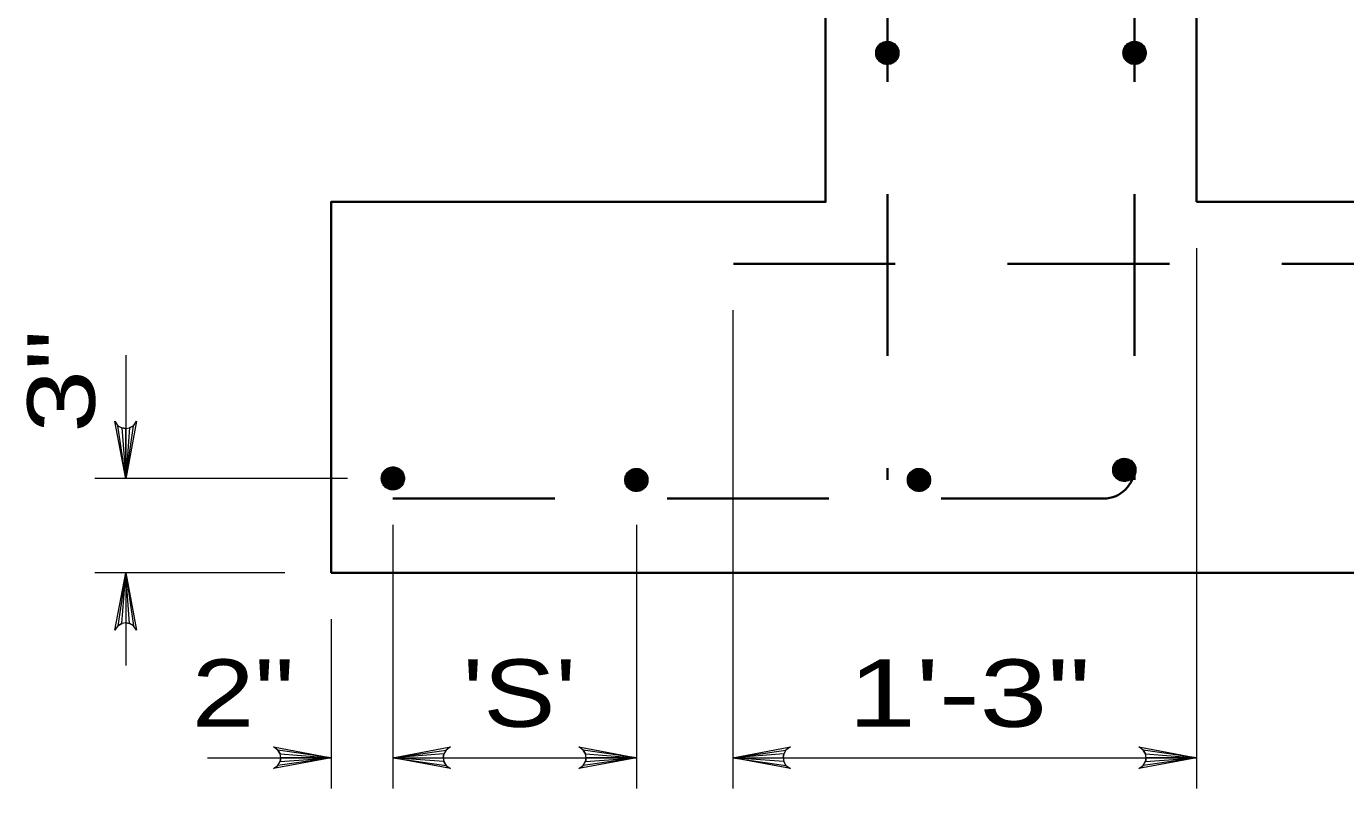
# Model space of a CAD drawing. Extents: x 394.95 to 401.96, y -76.51 to -66.78.
# Drawn here: x 399.118 to 400.292, y -68.199 to -67.52 of the extents above; entities that cross this region are included whole.
import ezdxf
from ezdxf.enums import TextEntityAlignment as Align

# ---------------------------------------------------------------- set-up
doc = ezdxf.new("R2010")
doc.units = 0
doc.header["$LTSCALE"] = 0.024
doc.linetypes.add('LONG_DASHED', pattern=[7.5, 6, -1.5])
doc.layers.add('1', color=7, linetype='LONG_DASHED', lineweight=35)
doc.layers.add('10', color=7, linetype='Continuous', lineweight=13)
doc.layers.add('12', color=7, linetype='Continuous')

msp = doc.modelspace()

# ---------------------------------------------------------------- linework, layer by layer
at = {"layer": '1', "linetype": 'Continuous'}
for p, q in [((400.15918, -67.6764), (400.15918, -67.1264)), ((399.38918, -68.0064), (400.43418, -68.0064))]:
    msp.add_line(p, q, dxfattribs=at)
at = {"layer": '1'}
for p, q in [((399.88418, -67.1814), (399.88418, -67.9239)), ((400.10418, -67.1814), (400.10418, -67.9239)), ((400.37918, -67.7314), (399.74668, -67.7314)), ((399.44418, -67.9404), (400.07668, -67.9404))]:
    msp.add_line(p, q, dxfattribs=at)
at = {"layer": '1', "linetype": 'Continuous'}
for points in [[(399.38918, -68.0064), (399.38918, -67.6764), (399.82918, -67.6764), (399.82918, -67.1264), (400.15918, -67.1264)], [(400.15918, -67.6764), (400.43418, -67.6764), (400.43418, -68.0064)]]:
    msp.add_lwpolyline(points, dxfattribs=at)
at = {"layer": '1', "lineweight": 13}
for points in [[(399.88144, -67.53425), (399.88465, -67.53369), (399.88843, -67.53481), (399.89241, -67.5383), (399.8938, -67.54164), (399.89384, -67.54565), (399.89175, -67.55014), (399.88875, -67.5528), (399.88542, -67.55364), (399.88165, -67.55352), (399.8784, -67.55195), (399.87618, -67.5499), (399.87478, -67.54681), (399.87412, -67.54335), (399.87498, -67.54015), (399.87658, -67.53742), (399.8792, -67.53525), (399.88144, -67.53432), (399.8873, -67.53437), (399.88027, -67.53477), (399.88867, -67.53481), (399.87843, -67.53536), (399.88982, -67.53557), (399.87795, -67.53601), (399.89047, -67.53609), (399.87727, -67.53654), (399.89127, -67.53678), (399.87662, -67.53714), (399.89187, -67.53729), (399.8763, -67.53774), (399.89211, -67.53782), (399.87585, -67.53818), (399.89268, -67.5383), (399.87561, -67.5385), (399.89284, -67.53878), (399.87543, -67.53902), (399.89312, -67.53914), (399.87522, -67.53943), (399.89336, -67.53958), (399.87466, -67.53999), (399.89353, -67.53999), (399.87457, -67.54059), (399.89365, -67.54031), (399.87445, -67.54127), (399.89384, -67.54095), (399.87421, -67.54204), (399.89389, -67.54148), (399.87433, -67.54172), (399.89412, -67.54196), (399.87418, -67.54252), (399.89409, -67.54247), (399.87409, -67.54296), (399.89421, -67.54287), (399.87405, -67.54341), (399.89421, -67.54324), (399.87418, -67.54404), (399.89421, -67.54372), (399.87409, -67.54452), (399.89433, -67.54424), (399.87401, -67.54376), (399.89421, -67.54469), (399.87412, -67.54493), (399.89428, -67.54512), (399.87418, -67.54536), (399.89409, -67.54561), (399.87425, -67.54577), (399.89396, -67.54601), (399.87442, -67.54629), (399.89389, -67.54636), (399.8745, -67.54674), (399.8938, -67.54685), (399.87481, -67.54725), (399.89372, -67.5473), (399.8749, -67.5477), (399.89353, -67.54761), (399.87502, -67.54818), (399.89329, -67.54802), (399.87534, -67.54861), (399.89316, -67.5485), (399.87558, -67.54902), (399.89289, -67.54894), (399.8757, -67.54939), (399.8926, -67.54946), (399.87602, -67.54978), (399.89235, -67.54982), (399.87634, -67.5501), (399.89192, -67.5503), (399.87682, -67.55062), (399.89135, -67.55078), (399.8773, -67.55118), (399.89075, -67.55131), (399.87799, -67.55186), (399.89031, -67.55171), (399.87923, -67.55251), (399.88987, -67.55227), (399.87887, -67.55227), (399.88919, -67.55264), (399.87968, -67.5528), (399.8883, -67.55307), (399.88031, -67.55311), (399.8873, -67.55344)], [(399.8873, -67.55344), (399.88373, -67.55387), (399.87843, -67.55043), (399.87519, -67.54332), (399.87995, -67.53529), (399.88691, -67.53445), (399.89228, -67.54062), (399.89228, -67.54725), (399.88891, -67.55216), (399.88333, -67.55323), (399.87703, -67.54995), (399.87931, -67.55183), (399.8753, -67.54131), (399.87906, -67.5355), (399.88461, -67.5339), (399.88871, -67.53574), (399.89216, -67.53975), (399.89369, -67.54303), (399.89187, -67.5495)], [(400.10144, -67.53425), (400.10465, -67.53369), (400.10843, -67.53481), (400.11241, -67.5383), (400.1138, -67.54164), (400.11384, -67.54565), (400.11175, -67.55014), (400.10875, -67.5528), (400.10542, -67.55364), (400.10165, -67.55352), (400.0984, -67.55195), (400.09618, -67.5499), (400.09478, -67.54681), (400.09412, -67.54335), (400.09498, -67.54015), (400.09658, -67.53742), (400.0992, -67.53525), (400.10144, -67.53432), (400.1073, -67.53437), (400.10027, -67.53477), (400.10867, -67.53481), (400.09843, -67.53536), (400.10982, -67.53557), (400.09795, -67.53601), (400.11047, -67.53609), (400.09727, -67.53654), (400.11127, -67.53678), (400.09662, -67.53714), (400.11187, -67.53729), (400.0963, -67.53774), (400.11211, -67.53782), (400.09585, -67.53818), (400.11268, -67.5383), (400.09561, -67.5385), (400.11284, -67.53878), (400.09543, -67.53902), (400.11312, -67.53914), (400.09522, -67.53943), (400.11336, -67.53958), (400.09466, -67.53999), (400.11353, -67.53999), (400.09457, -67.54059), (400.11365, -67.54031), (400.09445, -67.54127), (400.11384, -67.54095), (400.09421, -67.54204), (400.11389, -67.54148), (400.09433, -67.54172), (400.11413, -67.54196), (400.09418, -67.54252), (400.11409, -67.54247), (400.09409, -67.54296), (400.11421, -67.54287), (400.09405, -67.54341), (400.11421, -67.54324), (400.09418, -67.54404), (400.11421, -67.54372), (400.09409, -67.54452), (400.11433, -67.54424), (400.09401, -67.54376), (400.11421, -67.54469), (400.09412, -67.54493), (400.11428, -67.54512), (400.09418, -67.54536), (400.11409, -67.54561), (400.09425, -67.54577), (400.11396, -67.54601), (400.09442, -67.54629), (400.11389, -67.54636), (400.0945, -67.54674), (400.1138, -67.54685), (400.09481, -67.54725), (400.11372, -67.5473), (400.0949, -67.5477), (400.11353, -67.54761), (400.09502, -67.54818), (400.11329, -67.54802), (400.09534, -67.54861), (400.11316, -67.5485), (400.09558, -67.54902), (400.11289, -67.54894), (400.0957, -67.54939), (400.1126, -67.54946), (400.09602, -67.54978), (400.11235, -67.54982), (400.09634, -67.5501), (400.11192, -67.5503), (400.09682, -67.55062), (400.11135, -67.55078), (400.0973, -67.55118), (400.11075, -67.55131), (400.09799, -67.55186), (400.11031, -67.55171), (400.09923, -67.55251), (400.10987, -67.55227), (400.09887, -67.55227), (400.10919, -67.55264), (400.09968, -67.5528), (400.1083, -67.55307), (400.10031, -67.55311), (400.1073, -67.55344)], [(400.1073, -67.55344), (400.10373, -67.55387), (400.09843, -67.55043), (400.09519, -67.54332), (400.09995, -67.53529), (400.10691, -67.53445), (400.11228, -67.54062), (400.11228, -67.54725), (400.10891, -67.55216), (400.10333, -67.55323), (400.09703, -67.54995), (400.09931, -67.55183), (400.0953, -67.54131), (400.09906, -67.5355), (400.10461, -67.5339), (400.10871, -67.53574), (400.11216, -67.53975), (400.11369, -67.54303), (400.11187, -67.5495)], [(399.44144, -67.91296), (399.44465, -67.9124), (399.44843, -67.91352), (399.45241, -67.91701), (399.4538, -67.92033), (399.45384, -67.92435), (399.45175, -67.92884), (399.44875, -67.9315), (399.44542, -67.93234), (399.44165, -67.93222), (399.4384, -67.93066), (399.43618, -67.9286), (399.43478, -67.92551), (399.43412, -67.92206), (399.43498, -67.91885), (399.43658, -67.91612), (399.4392, -67.91395), (399.44144, -67.91303), (399.4473, -67.91307), (399.44027, -67.91347), (399.44867, -67.91352), (399.43843, -67.91408), (399.44982, -67.91427), (399.43795, -67.91472), (399.45047, -67.9148), (399.43727, -67.91524), (399.45127, -67.91548), (399.43662, -67.91584), (399.45187, -67.916), (399.4363, -67.91645), (399.45211, -67.91653), (399.43585, -67.91689), (399.45268, -67.91701), (399.43561, -67.91721), (399.45284, -67.91749), (399.43543, -67.91773), (399.45312, -67.91784), (399.43522, -67.91814), (399.45336, -67.91829), (399.43466, -67.9187), (399.45353, -67.9187), (399.43457, -67.91929), (399.45365, -67.91902), (399.43445, -67.91998), (399.45384, -67.91966), (399.43421, -67.92074), (399.45389, -67.92018), (399.43433, -67.92042), (399.45412, -67.92066), (399.43418, -67.92122), (399.45409, -67.92119), (399.43409, -67.92167), (399.45421, -67.92158), (399.43405, -67.92211), (399.45421, -67.92195), (399.43418, -67.92275), (399.45421, -67.92243), (399.43409, -67.92323), (399.45433, -67.92295), (399.43401, -67.92247), (399.45421, -67.9234), (399.43412, -67.92364), (399.45428, -67.92383), (399.43418, -67.92407), (399.45409, -67.92431), (399.43425, -67.92447), (399.45396, -67.92471), (399.43442, -67.925), (399.45389, -67.92508), (399.4345, -67.92544), (399.4538, -67.92556), (399.43481, -67.92596), (399.45372, -67.926), (399.4349, -67.9264), (399.45353, -67.92631), (399.43502, -67.92687), (399.45329, -67.92672), (399.43534, -67.92732), (399.45316, -67.9272), (399.43558, -67.92773), (399.45289, -67.92765), (399.4357, -67.92809), (399.4526, -67.92818), (399.43602, -67.92849), (399.45235, -67.92853), (399.43634, -67.92881), (399.45192, -67.92901), (399.43682, -67.92933), (399.45135, -67.92949), (399.4373, -67.9299), (399.45075, -67.93002), (399.43799, -67.93058), (399.45031, -67.93042), (399.43923, -67.93122), (399.44987, -67.93098), (399.43887, -67.93098), (399.44919, -67.93133), (399.43968, -67.9315), (399.4483, -67.93178), (399.44031, -67.93181), (399.4473, -67.93214)], [(399.4473, -67.93214), (399.44373, -67.93258), (399.43843, -67.92914), (399.43519, -67.92203), (399.43995, -67.914), (399.44691, -67.91315), (399.45228, -67.91933), (399.45228, -67.92596), (399.44891, -67.93085), (399.44333, -67.93194), (399.43703, -67.92866), (399.43931, -67.93053), (399.4353, -67.92001), (399.43906, -67.9142), (399.44461, -67.91259), (399.44871, -67.91444), (399.45216, -67.91846), (399.45369, -67.92174), (399.45187, -67.92821)], [(399.6581, -67.91434), (399.66131, -67.91378), (399.66509, -67.91491), (399.66907, -67.9184), (399.67047, -67.92173), (399.67051, -67.92574), (399.66842, -67.93024), (399.66542, -67.9329), (399.66208, -67.93373), (399.65831, -67.93361), (399.65505, -67.93204), (399.65284, -67.92999), (399.65145, -67.92692), (399.65079, -67.92345), (399.65165, -67.92024), (399.65325, -67.91752), (399.65585, -67.91535), (399.6581, -67.91443), (399.66397, -67.91447), (399.65694, -67.91486), (399.66533, -67.91491), (399.65509, -67.91547), (399.66649, -67.91567), (399.65461, -67.9161), (399.66714, -67.91619), (399.65394, -67.91664), (399.66794, -67.91688), (399.65329, -67.91723), (399.66854, -67.91739), (399.65297, -67.91783), (399.66878, -67.91792), (399.65252, -67.91827), (399.66934, -67.9184), (399.65228, -67.91859), (399.66951, -67.91887), (399.65209, -67.91912), (399.66979, -67.91925), (399.65189, -67.91952), (399.67003, -67.91968), (399.65132, -67.92008), (399.6702, -67.92008), (399.65124, -67.92069), (399.67031, -67.92041), (399.65111, -67.92136), (399.67051, -67.92104), (399.65087, -67.92214), (399.67055, -67.92157), (399.651, -67.92181), (399.67079, -67.92205), (399.65084, -67.92261), (399.67075, -67.92257), (399.65076, -67.92305), (399.67086, -67.92297), (399.65072, -67.9235), (399.67086, -67.92333), (399.65084, -67.92414), (399.67086, -67.92382), (399.65076, -67.92462), (399.671, -67.92433), (399.65068, -67.92385), (399.67086, -67.92478), (399.65079, -67.92502), (399.67095, -67.92523), (399.65084, -67.92547), (399.67075, -67.92571), (399.65092, -67.92586), (399.67062, -67.92611), (399.65108, -67.92639), (399.67055, -67.92647), (399.65116, -67.92683), (399.67047, -67.92695), (399.65148, -67.92734), (399.67039, -67.9274), (399.65156, -67.92779), (399.6702, -67.92772), (399.65169, -67.92827), (399.66995, -67.92811), (399.65201, -67.92871), (399.66982, -67.92859), (399.65225, -67.92911), (399.66955, -67.92903), (399.65236, -67.92948), (399.66926, -67.92956), (399.65269, -67.92987), (399.66902, -67.92992), (399.65301, -67.9302), (399.66857, -67.9304), (399.65349, -67.93073), (399.66802, -67.93089), (399.65397, -67.93129), (399.66742, -67.93141), (399.65466, -67.93197), (399.66697, -67.9318), (399.6559, -67.9326), (399.66654, -67.93236), (399.65554, -67.93236), (399.66585, -67.93273), (399.65634, -67.9329), (399.66497, -67.93317), (399.65698, -67.93322), (399.66397, -67.93353)], [(399.66397, -67.93353), (399.6604, -67.93397), (399.65509, -67.93052), (399.65184, -67.92342), (399.65661, -67.91539), (399.66357, -67.91455), (399.66895, -67.92073), (399.66895, -67.92734), (399.66557, -67.93225), (399.66, -67.93333), (399.6537, -67.93004), (399.65597, -67.93193), (399.65196, -67.92142), (399.65573, -67.91559), (399.66128, -67.91399), (399.66536, -67.91583), (399.66882, -67.91984), (399.67035, -67.92314), (399.66854, -67.92959)], [(399.9096, -67.91434), (399.91281, -67.91378), (399.91659, -67.91491), (399.92057, -67.9184), (399.92197, -67.92173), (399.92201, -67.92574), (399.91992, -67.93024), (399.91692, -67.9329), (399.91358, -67.93373), (399.90981, -67.93361), (399.90655, -67.93204), (399.90434, -67.92999), (399.90295, -67.92692), (399.90229, -67.92345), (399.90315, -67.92024), (399.90475, -67.91752), (399.90735, -67.91535), (399.9096, -67.91443), (399.91547, -67.91447), (399.90844, -67.91486), (399.91683, -67.91491), (399.90659, -67.91547), (399.91799, -67.91567), (399.9061, -67.9161), (399.91864, -67.91619), (399.90544, -67.91664), (399.91944, -67.91688), (399.90479, -67.91723), (399.92004, -67.91739), (399.90447, -67.91783), (399.92028, -67.91792), (399.90402, -67.91827), (399.92084, -67.9184), (399.90378, -67.91859), (399.921, -67.91887), (399.90358, -67.91912), (399.92129, -67.91925), (399.90339, -67.91952), (399.92153, -67.91968), (399.90282, -67.92008), (399.92169, -67.92008), (399.90274, -67.92069), (399.9218, -67.92041), (399.90263, -67.92136), (399.92201, -67.92104), (399.90238, -67.92214), (399.92205, -67.92157), (399.9025, -67.92181), (399.92229, -67.92205), (399.90234, -67.92261), (399.92225, -67.92257), (399.90226, -67.92305), (399.92236, -67.92297), (399.90221, -67.9235), (399.92236, -67.92333), (399.90234, -67.92414), (399.92236, -67.92382), (399.90226, -67.92462), (399.92249, -67.92433), (399.90218, -67.92385), (399.92236, -67.92478), (399.90229, -67.92502), (399.92245, -67.92523), (399.90234, -67.92547), (399.92225, -67.92571), (399.90242, -67.92586), (399.92212, -67.92611), (399.90258, -67.92639), (399.92205, -67.92647), (399.90266, -67.92683), (399.92197, -67.92695), (399.90298, -67.92734), (399.92189, -67.9274), (399.90306, -67.92779), (399.92169, -67.92772), (399.90319, -67.92827), (399.92145, -67.92811), (399.90351, -67.92871), (399.92132, -67.92859), (399.90375, -67.92911), (399.92105, -67.92903), (399.90386, -67.92948), (399.92076, -67.92956), (399.90419, -67.92987), (399.92052, -67.92992), (399.9045, -67.9302), (399.92007, -67.9304), (399.90499, -67.93073), (399.91951, -67.93089), (399.90547, -67.93129), (399.91892, -67.93141), (399.90616, -67.93197), (399.91847, -67.9318), (399.9074, -67.9326), (399.91804, -67.93236), (399.90704, -67.93236), (399.91735, -67.93273), (399.90784, -67.9329), (399.91647, -67.93317), (399.90848, -67.93322), (399.91547, -67.93353)], [(399.91547, -67.93353), (399.9119, -67.93397), (399.90659, -67.93052), (399.90334, -67.92342), (399.90811, -67.91539), (399.91507, -67.91455), (399.92045, -67.92073), (399.92045, -67.92734), (399.91707, -67.93225), (399.91149, -67.93333), (399.90519, -67.93004), (399.90747, -67.93193), (399.90346, -67.92142), (399.90723, -67.91559), (399.91278, -67.91399), (399.91686, -67.91583), (399.92033, -67.91984), (399.92185, -67.92314), (399.92004, -67.92959)], [(400.09234, -67.9054), (400.09555, -67.90483), (400.09933, -67.90596), (400.10329, -67.90945), (400.10471, -67.91277), (400.10475, -67.91679), (400.10266, -67.92128), (400.09966, -67.92394), (400.09631, -67.92478), (400.09255, -67.92466), (400.08929, -67.92309), (400.08708, -67.92104), (400.08568, -67.91795), (400.08503, -67.9145), (400.08587, -67.91129), (400.08748, -67.90856), (400.09009, -67.90639), (400.09234, -67.90547), (400.0982, -67.90551), (400.09118, -67.90591), (400.09957, -67.90596), (400.08932, -67.90652), (400.10073, -67.90671), (400.08884, -67.90716), (400.10137, -67.90724), (400.08817, -67.90768), (400.10218, -67.90792), (400.08753, -67.90828), (400.10278, -67.90844), (400.08721, -67.90889), (400.10302, -67.90897), (400.08676, -67.90932), (400.10358, -67.90945), (400.08652, -67.90965), (400.10374, -67.90993), (400.08631, -67.91017), (400.10402, -67.91028), (400.08611, -67.91057), (400.10427, -67.91073), (400.08556, -67.91114), (400.10443, -67.91114), (400.08548, -67.91173), (400.10454, -67.91146), (400.08535, -67.91242), (400.10475, -67.91209), (400.08511, -67.91318), (400.10478, -67.91261), (400.08524, -67.91285), (400.10502, -67.91309), (400.08507, -67.91366), (400.10499, -67.91362), (400.085, -67.9141), (400.1051, -67.91402), (400.08495, -67.91455), (400.1051, -67.91439), (400.08507, -67.91519), (400.1051, -67.91486), (400.085, -67.91567), (400.10523, -67.91539), (400.08492, -67.91491), (400.1051, -67.91583), (400.08503, -67.91607), (400.10519, -67.91627), (400.08507, -67.91651), (400.10499, -67.91675), (400.08516, -67.91691), (400.10486, -67.91715), (400.08531, -67.91744), (400.10478, -67.91752), (400.0854, -67.91787), (400.10471, -67.918), (400.08572, -67.9184), (400.10462, -67.91844), (400.0858, -67.91883), (400.10443, -67.91875), (400.08592, -67.91931), (400.10419, -67.91916), (400.08623, -67.91976), (400.10406, -67.91964), (400.08649, -67.92017), (400.10378, -67.92008), (400.0866, -67.92053), (400.1035, -67.92061), (400.08692, -67.92093), (400.10326, -67.92097), (400.08724, -67.92125), (400.10281, -67.92145), (400.08772, -67.92177), (400.10225, -67.92193), (400.08821, -67.92233), (400.10166, -67.92246), (400.0889, -67.92302), (400.10121, -67.92285), (400.09013, -67.92366), (400.10077, -67.92342), (400.08977, -67.92342), (400.10008, -67.92377), (400.09057, -67.92394), (400.09921, -67.92422), (400.09122, -67.92425), (400.0982, -67.92457)], [(400.0982, -67.92457), (400.09464, -67.92502), (400.08932, -67.92157), (400.08607, -67.91447), (400.09085, -67.90644), (400.09779, -67.90558), (400.10318, -67.91177), (400.10318, -67.9184), (400.09981, -67.92329), (400.09423, -67.92437), (400.08793, -67.92109), (400.09021, -67.92297), (400.0862, -67.91245), (400.08997, -67.90664), (400.09551, -67.90503), (400.0996, -67.90687), (400.10305, -67.9109), (400.10459, -67.91418), (400.10278, -67.92065)]]:
    msp.add_lwpolyline(points, dxfattribs=at)
for centre in [(399.88418, -67.5438), (400.10418, -67.5438), (399.44418, -67.9225), (399.66084, -67.9239), (399.91234, -67.9239), (400.09508, -67.91494)]:
    msp.add_circle(centre, 0.01031, dxfattribs=at)
at = {"layer": '1'}
msp.add_arc((400.07668, -67.9129), 0.0275, 270, 0, dxfattribs=at)
at = {"layer": '10'}
for p, q in [((400.15918, -67.71765), (400.15918, -68.19861)), ((399.74668, -67.77265), (399.74668, -68.19861)), ((399.20641, -67.81289), (399.20641, -67.92289)), ((399.40383, -67.92251), (399.17891, -67.92251)), ((399.44418, -67.96376), (399.44418, -68.19861)), ((399.66084, -67.96376), (399.66084, -68.19861)), ((399.34793, -68.0064), (399.17891, -68.0064)), ((399.20641, -68.0064), (399.20641, -68.0889)), ((399.38918, -68.04765), (399.38918, -68.19861)), ((399.27918, -68.17111), (399.38918, -68.17111)), ((399.44418, -68.17111), (399.66084, -68.17111)), ((399.74668, -68.17111), (400.15918, -68.17111))]:
    msp.add_line(p, q, dxfattribs=at)
for points in [[(399.20641, -67.92289), (399.19679, -67.87162), (399.19953, -67.87558), (399.20297, -67.8776), (399.20641, -67.8782), (399.20984, -67.8776), (399.21328, -67.87558), (399.21601, -67.87162), (399.20641, -67.92289), (399.21328, -67.87558), (399.20984, -67.8776), (399.20641, -67.92289), (399.20641, -67.8782), (399.20297, -67.8776), (399.20641, -67.92289), (399.19953, -67.87558)], [(399.20641, -68.0064), (399.21601, -68.05767), (399.21328, -68.05371), (399.20984, -68.05167), (399.20641, -68.05108), (399.20297, -68.05167), (399.19953, -68.05371), (399.19679, -68.05767), (399.20641, -68.0064), (399.19953, -68.05371), (399.20297, -68.05167), (399.20641, -68.0064), (399.20641, -68.05108), (399.20984, -68.05167), (399.20641, -68.0064), (399.21328, -68.05371)], [(399.38918, -68.17111), (399.33792, -68.18073), (399.34186, -68.17799), (399.34391, -68.17455), (399.34449, -68.17111), (399.34391, -68.16768), (399.34186, -68.16424), (399.33792, -68.1615), (399.38918, -68.17111), (399.34186, -68.16424), (399.34391, -68.16768), (399.38918, -68.17111), (399.34449, -68.17111), (399.34391, -68.17455), (399.38918, -68.17111), (399.34186, -68.17799)], [(399.44418, -68.17111), (399.49544, -68.1615), (399.49149, -68.16424), (399.48946, -68.16768), (399.48886, -68.17111), (399.48946, -68.17455), (399.49149, -68.17799), (399.49544, -68.18073), (399.44418, -68.17111), (399.49149, -68.17799), (399.48946, -68.17455), (399.44418, -68.17111), (399.48886, -68.17111), (399.48946, -68.16768), (399.44418, -68.17111), (399.49149, -68.16424)], [(399.66084, -68.17111), (399.60958, -68.18073), (399.61353, -68.17799), (399.61557, -68.17455), (399.61616, -68.17111), (399.61557, -68.16768), (399.61353, -68.16424), (399.60958, -68.1615), (399.66084, -68.17111), (399.61353, -68.16424), (399.61557, -68.16768), (399.66084, -68.17111), (399.61616, -68.17111), (399.61557, -68.17455), (399.66084, -68.17111), (399.61353, -68.17799)], [(399.74668, -68.17111), (399.79794, -68.1615), (399.79399, -68.16424), (399.79196, -68.16768), (399.79136, -68.17111), (399.79196, -68.17455), (399.79399, -68.17799), (399.79794, -68.18073), (399.74668, -68.17111), (399.79399, -68.17799), (399.79196, -68.17455), (399.74668, -68.17111), (399.79136, -68.17111), (399.79196, -68.16768), (399.74668, -68.17111), (399.79399, -68.16424)], [(400.15918, -68.17111), (400.10792, -68.18073), (400.11186, -68.17799), (400.11391, -68.17455), (400.11449, -68.17111), (400.11391, -68.16768), (400.11186, -68.16424), (400.10792, -68.1615), (400.15918, -68.17111), (400.11186, -68.16424), (400.11391, -68.16768), (400.15918, -68.17111), (400.11449, -68.17111), (400.11391, -68.17455), (400.15918, -68.17111), (400.11186, -68.17799)]]:
    msp.add_lwpolyline(points, dxfattribs=at)

# ---------------------------------------------------------------- texts
at = {"layer": '12', "width": 1.25}
msp.add_text('3"', height=0.06, rotation=90, dxfattribs=at).set_placement((399.17891, -67.83615), align=Align.CENTER)
at = {"layer": '12'}
for s, width, p in [('2"', 1.25, (399.3109, -68.1436)), ("'S'", 1.2, (399.55672, -68.1436)), ('1\'-3"', 1.35, (399.95715, -68.1436))]:
    msp.add_text(s, height=0.06, dxfattribs=dict(at, width=width)).set_placement(p, align=Align.CENTER)

doc.saveas('drawing.dxf')
